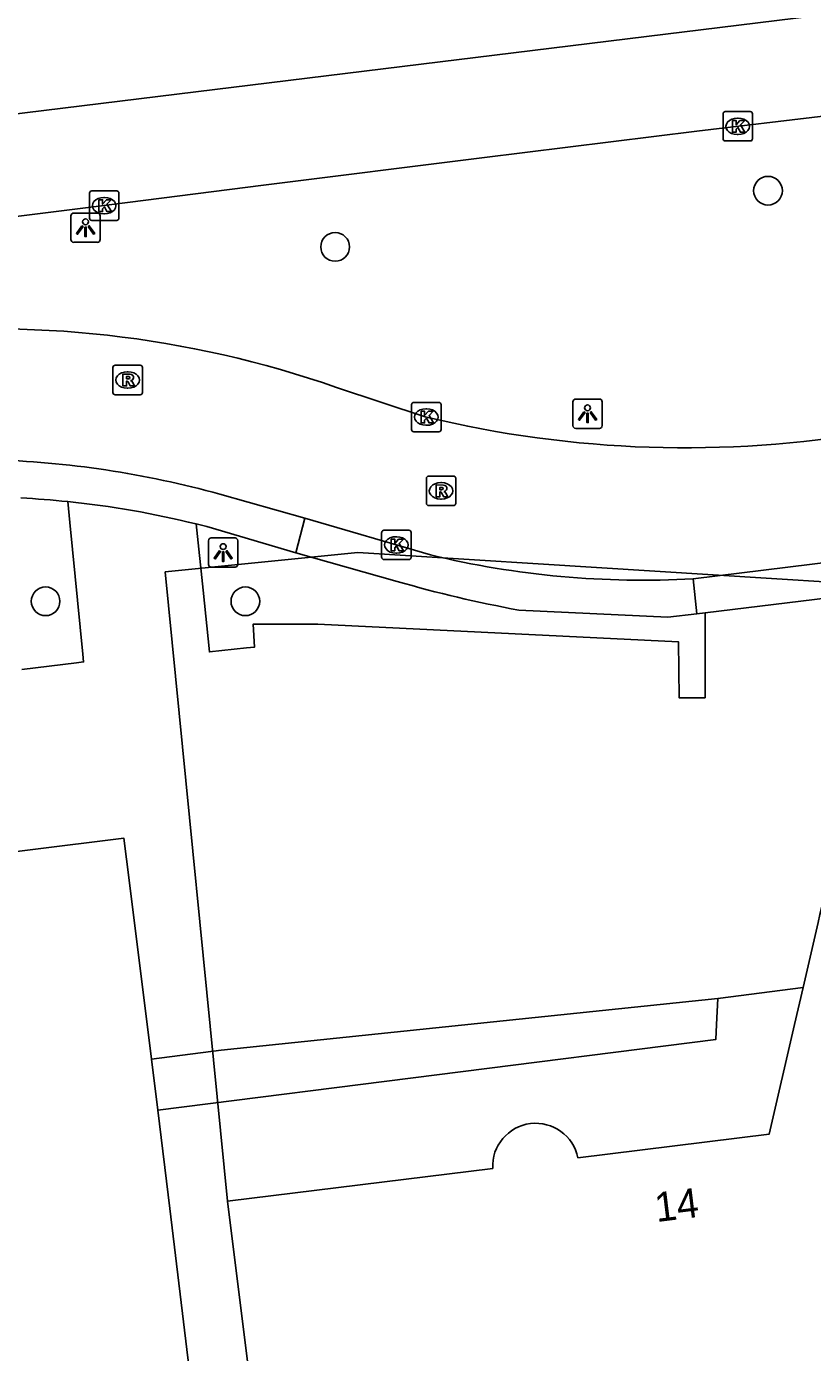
# Model space of a CAD drawing. Extents: x 161477 to 163040, y 383680 to 384868.
# Drawn here: x 161958.93 to 161985.69, y 383988.83 to 384033.98 of the extents above; entities that cross this region are included whole.
import ezdxf

# ---------------------------------------------------------------- set-up
doc = ezdxf.new("R2010")
doc.units = 0
for name, color, linetype in [('IMGEO_Boom', 7, 'Continuous'), ('IMGEO_Kolk', 7, 'Continuous'), ('IMGEO_Lichtpunt', 7, 'Continuous'), ('IMGEO_Pand', 7, 'Continuous'), ('IMGEO_Pand_nummerreeks', 7, 'Continuous'), ('IMGEO_Pand_overbouw', 7, 'Continuous'), ('IMGEO_Rijbaan_lokaal_gesloten', 7, 'Continuous'), ('IMGEO_Rijbaan_lokaal_open', 7, 'Continuous'), ('IMGEO_Rioolput', 7, 'Continuous'), ('IMGEO_Voetpad_open', 7, 'Continuous')]:
    doc.layers.add(name, color=color, linetype=linetype)

msp = doc.modelspace()

# ---------------------------------------------------------------- linework, layer by layer
at = {"layer": 'IMGEO_Boom'}
for centre in [(161984.176, 384028.393), (161969.437, 384026.48), (161959.577, 384014.412), (161966.381, 384014.412)]:
    msp.add_circle(centre, 0.489, dxfattribs=at)
at = {"layer": 'IMGEO_Kolk'}
for p, q in [((161982.645, 384030.161), (161982.645, 384031.013)), ((161982.72, 384031.087), (161983.572, 384031.087)), ((161983.646, 384031.013), (161983.646, 384030.161)), ((161983.133, 384030.867), (161983.158, 384030.867)), ((161983.572, 384030.087), (161982.72, 384030.087)), ((161983.156, 384030.307), (161983.131, 384030.307)), ((161961.072, 384027.458), (161961.072, 384028.31)), ((161961.147, 384028.384), (161961.999, 384028.384)), ((161962.073, 384028.31), (161962.073, 384027.458)), ((161961.56, 384028.164), (161961.585, 384028.164)), ((161961.999, 384027.384), (161961.147, 384027.384)), ((161961.583, 384027.604), (161961.558, 384027.604)), ((161972.041, 384020.259), (161972.041, 384021.111)), ((161972.116, 384021.185), (161972.968, 384021.185)), ((161972.529, 384020.965), (161972.554, 384020.965)), ((161973.042, 384021.111), (161973.042, 384020.259)), ((161972.968, 384020.185), (161972.116, 384020.185)), ((161972.552, 384020.405), (161972.527, 384020.405)), ((161971.021, 384015.905), (161971.021, 384016.757)), ((161971.096, 384016.831), (161971.948, 384016.831)), ((161971.509, 384016.611), (161971.534, 384016.611)), ((161972.022, 384016.757), (161972.022, 384015.905)), ((161971.532, 384016.051), (161971.507, 384016.051)), ((161971.948, 384015.831), (161971.096, 384015.831))]:
    msp.add_line(p, q, dxfattribs=at)
for points in [[(161982.645, 384030.161), (161982.645, 384031.013)], [(161982.72, 384031.087), (161983.572, 384031.087)], [(161983.646, 384031.013), (161983.646, 384030.161)], [(161982.966, 384030.787), (161983.089, 384030.787), (161983.089, 384030.636), (161983.219, 384030.787), (161983.383, 384030.787), (161983.237, 384030.636), (161983.39, 384030.387), (161983.238, 384030.387), (161983.153, 384030.551), (161983.089, 384030.484), (161983.089, 384030.387), (161982.966, 384030.387), (161982.966, 384030.787)], [(161983.572, 384030.087), (161982.72, 384030.087)], [(161961.072, 384027.458), (161961.072, 384028.31)], [(161961.147, 384028.384), (161961.999, 384028.384)], [(161962.073, 384028.31), (161962.073, 384027.458)], [(161961.393, 384028.084), (161961.516, 384028.084), (161961.516, 384027.933), (161961.646, 384028.084), (161961.81, 384028.084), (161961.664, 384027.933), (161961.817, 384027.684), (161961.665, 384027.684), (161961.58, 384027.848), (161961.516, 384027.781), (161961.516, 384027.684), (161961.393, 384027.684), (161961.393, 384028.084)], [(161961.999, 384027.384), (161961.147, 384027.384)], [(161972.041, 384020.259), (161972.041, 384021.111)], [(161972.116, 384021.185), (161972.968, 384021.185)], [(161973.042, 384021.111), (161973.042, 384020.259)], [(161972.362, 384020.885), (161972.485, 384020.885), (161972.485, 384020.734), (161972.615, 384020.885), (161972.779, 384020.885), (161972.633, 384020.734), (161972.786, 384020.485), (161972.634, 384020.485), (161972.549, 384020.649), (161972.485, 384020.582), (161972.485, 384020.485), (161972.362, 384020.485), (161972.362, 384020.885)], [(161972.968, 384020.185), (161972.116, 384020.185)], [(161971.021, 384015.905), (161971.021, 384016.757)], [(161971.096, 384016.831), (161971.948, 384016.831)], [(161971.342, 384016.531), (161971.465, 384016.531), (161971.465, 384016.38), (161971.595, 384016.531), (161971.759, 384016.531), (161971.613, 384016.38), (161971.766, 384016.131), (161971.614, 384016.131), (161971.529, 384016.295), (161971.465, 384016.228), (161971.465, 384016.131), (161971.342, 384016.131), (161971.342, 384016.531)], [(161972.022, 384016.757), (161972.022, 384015.905)], [(161971.948, 384015.831), (161971.096, 384015.831)]]:
    msp.add_lwpolyline(points, dxfattribs=at)
for centre, start, end in [((161982.722, 384031.011), 91.552, 178.448), ((161982.722, 384031.011), 91.552, 178.448), ((161983.57, 384031.011), 1.552, 88.448), ((161983.57, 384031.011), 1.552, 88.448), ((161982.722, 384030.163), 181.552, 268.448), ((161982.722, 384030.163), 181.552, 268.448), ((161983.57, 384030.163), 271.552, 358.448), ((161983.57, 384030.163), 271.552, 358.448), ((161961.149, 384028.308), 91.552, 178.448), ((161961.149, 384028.308), 91.552, 178.448), ((161961.997, 384028.308), 1.552, 88.448), ((161961.997, 384028.308), 1.552, 88.448), ((161961.149, 384027.46), 181.552, 268.448), ((161961.149, 384027.46), 181.552, 268.448), ((161961.997, 384027.46), 271.552, 358.448), ((161961.997, 384027.46), 271.552, 358.448), ((161972.118, 384021.109), 91.552, 178.448), ((161972.118, 384021.109), 91.552, 178.448), ((161972.966, 384021.109), 1.552, 88.448), ((161972.966, 384021.109), 1.552, 88.448), ((161972.118, 384020.261), 181.552, 268.448), ((161972.118, 384020.261), 181.552, 268.448), ((161972.966, 384020.261), 271.552, 358.448), ((161972.966, 384020.261), 271.552, 358.448), ((161971.098, 384016.755), 91.552, 178.448), ((161971.098, 384016.755), 91.552, 178.448), ((161971.946, 384016.755), 1.552, 88.448), ((161971.946, 384016.755), 1.552, 88.448), ((161971.098, 384015.907), 181.552, 268.448), ((161971.098, 384015.907), 181.552, 268.448), ((161971.946, 384015.907), 271.552, 358.448), ((161971.946, 384015.907), 271.552, 358.448)]:
    msp.add_arc(centre, 0.0765, start, end, dxfattribs=at)
for centre, major_axis, ratio, start_param, end_param in [((161983.132, 384030.587), (-0.387, 0.002), 0.722429, 4.712389, 7.853982), ((161983.157, 384030.587), (-0.39, 0.002), 0.717154, 1.570796, 4.712389), ((161961.559, 384027.884), (-0.387, 0.002), 0.722429, 4.712389, 7.853982), ((161961.584, 384027.884), (-0.39, 0.002), 0.717154, 1.570796, 4.712389), ((161972.528, 384020.685), (-0.387, 0.002), 0.722429, 4.712389, 7.853982), ((161972.553, 384020.685), (-0.39, 0.002), 0.717154, 1.570796, 4.712389), ((161971.508, 384016.331), (-0.387, 0.002), 0.722429, 4.712389, 7.853982), ((161971.533, 384016.331), (-0.39, 0.002), 0.717154, 1.570796, 4.712389)]:
    msp.add_ellipse(centre, major_axis=major_axis, ratio=ratio, start_param=start_param, end_param=end_param, dxfattribs=at)
at = {"layer": 'IMGEO_Lichtpunt'}
for p, q in [((161960.44, 384027.537), (161960.44, 384026.73)), ((161960.44, 384027.537), (161960.44, 384026.73)), ((161961.342, 384027.632), (161960.534, 384027.632)), ((161961.342, 384027.632), (161960.534, 384027.632)), ((161961.436, 384026.73), (161961.436, 384027.537)), ((161961.436, 384026.73), (161961.436, 384027.537)), ((161960.534, 384026.636), (161961.342, 384026.636)), ((161960.534, 384026.636), (161961.342, 384026.636)), ((161977.534, 384021.202), (161977.534, 384020.395)), ((161977.534, 384021.202), (161977.534, 384020.395)), ((161978.436, 384021.297), (161977.628, 384021.297)), ((161978.436, 384021.297), (161977.628, 384021.297)), ((161978.53, 384020.395), (161978.53, 384021.202)), ((161978.53, 384020.395), (161978.53, 384021.202)), ((161977.628, 384020.301), (161978.436, 384020.301)), ((161977.628, 384020.301), (161978.436, 384020.301)), ((161965.125, 384016.475), (161965.125, 384015.668)), ((161965.125, 384016.475), (161965.125, 384015.668)), ((161966.027, 384016.57), (161965.219, 384016.57)), ((161966.027, 384016.57), (161965.219, 384016.57)), ((161966.121, 384015.668), (161966.121, 384016.475)), ((161966.121, 384015.668), (161966.121, 384016.475)), ((161965.219, 384015.574), (161966.027, 384015.574)), ((161965.219, 384015.574), (161966.027, 384015.574))]:
    msp.add_line(p, q, dxfattribs=at)
for points in [[(161960.814, 384027.201), (161960.853, 384027.173), (161960.665, 384026.911), (161960.627, 384026.938), (161960.814, 384027.201)], [(161960.916, 384027.153), (161960.963, 384027.153), (161960.963, 384026.831), (161960.916, 384026.831), (161960.916, 384027.153)], [(161961.026, 384027.173), (161961.064, 384027.2), (161961.251, 384026.938), (161961.212, 384026.91), (161961.026, 384027.173)], [(161977.908, 384020.866), (161977.947, 384020.838), (161977.759, 384020.576), (161977.721, 384020.603), (161977.908, 384020.866)], [(161978.01, 384020.818), (161978.057, 384020.818), (161978.057, 384020.496), (161978.01, 384020.496), (161978.01, 384020.818)], [(161978.12, 384020.838), (161978.158, 384020.865), (161978.345, 384020.603), (161978.306, 384020.575), (161978.12, 384020.838)], [(161965.499, 384016.139), (161965.538, 384016.111), (161965.35, 384015.849), (161965.312, 384015.876), (161965.499, 384016.139)], [(161965.601, 384016.091), (161965.648, 384016.091), (161965.648, 384015.769), (161965.601, 384015.769), (161965.601, 384016.091)], [(161965.711, 384016.111), (161965.749, 384016.138), (161965.936, 384015.876), (161965.897, 384015.848), (161965.711, 384016.111)]]:
    msp.add_lwpolyline(points, dxfattribs=at)
for centre in [(161960.939, 384027.335), (161978.033, 384021), (161965.624, 384016.273)]:
    msp.add_circle(centre, 0.0994, dxfattribs=at)
for centre, start, end in [((161960.534, 384027.537), 90, 180), ((161960.534, 384027.537), 90, 180), ((161961.342, 384027.537), 0, 90), ((161961.342, 384027.537), 0, 90), ((161960.534, 384026.73), 180, 270), ((161960.534, 384026.73), 180, 270), ((161961.342, 384026.73), 270, 0), ((161961.342, 384026.73), 270, 360), ((161977.628, 384021.202), 90, 180), ((161977.628, 384021.202), 90, 180), ((161978.436, 384021.202), 0, 90), ((161978.436, 384021.202), 0, 90), ((161977.628, 384020.395), 180, 270), ((161977.628, 384020.395), 180, 270), ((161978.436, 384020.395), 270, 0), ((161978.436, 384020.395), 270, 360), ((161965.219, 384016.475), 90, 180), ((161965.219, 384016.475), 90, 180), ((161966.027, 384016.475), 0, 90), ((161966.027, 384016.475), 0, 90), ((161965.219, 384015.668), 180, 270), ((161965.219, 384015.668), 180, 270), ((161966.027, 384015.668), 270, 0), ((161966.027, 384015.668), 270, 360)]:
    msp.add_arc(centre, 0.0946, start, end, dxfattribs=at)
at = {"layer": 'IMGEO_Pand'}
for points in [[(161952.749, 384005.163), (161962.246, 384006.341), (161962.423, 384004.917), (161963.181, 383998.816)], [(161985.371, 384001.262), (161985.88, 384003.477), (161985.946, 384003.746), (161986.011, 384004.007)], [(161977.701, 383995.458), (161984.214, 383996.262), (161985.079, 384000), (161985.371, 384001.262)], [(161963.396, 383997.077), (161963.181, 383998.816)], [(161963.396, 383997.077), (161963.811, 383993.739), (161964.461, 383988.274), (161965.92, 383976.575), (161968.408, 383956.619), (161969.073, 383951.131), (161955.356, 383949.45), (161955.133, 383951.147), (161955.119, 383951.24), (161924.788, 383947.478)], [(161981.129, 383955.114), (161980.959, 383954.521), (161974.903, 383955.916), (161978.261, 383970.442), (161975.409, 383985.765), (161966.543, 383987.797), (161965.767, 383993.981), (161974.802, 383995.101)]]:
    msp.add_lwpolyline(points, dxfattribs=at)
msp.add_arc((161976.265, 383995.171), 1.465, 11.2833, 182.7575, dxfattribs=at)
at = {"layer": 'IMGEO_Pand_overbouw'}
for points in [[(161977.701, 383995.458), (161984.214, 383996.262), (161985.079, 384000), (161985.371, 384001.262), (161985.88, 384003.477), (161985.946, 384003.746), (161986.011, 384004.007), (161986.378, 384003.925), (161986.327, 384003.735), (161991.48, 384003.456), (161991.454, 384003.664), (161991.801, 384003.707), (161991.39, 384006.662), (161991.261, 384007.832), (161991.117, 384009.147), (161990.439, 384014.803), (161970.21, 384016.077), (161963.654, 384015.417)], [(161963.654, 384015.417), (161965.767, 383993.981), (161974.802, 383995.101)]]:
    msp.add_lwpolyline(points, dxfattribs=at)
msp.add_arc((161976.265, 383995.171), 1.465, 11.2833, 182.7575, dxfattribs=at)
at = {"layer": 'IMGEO_Rijbaan_lokaal_gesloten'}
for points in [[(161696.618, 383999.076), (161717.081, 384001.544), (161768.879, 384007.897), (161825.477, 384014.75), (161917.35, 384025.954), (162007.495, 384037.033), (162008.923, 384037.209), (162102.422, 384048.613), (162177.172, 384057.667), (162248.391, 384066.39)], [(162036.516, 384037.016), (162009.54, 384033.893), (162008.109, 384033.699), (162000, 384032.599), (161996.88, 384032.194), (161990.538, 384031.465), (161981.752, 384030.422), (161974.434, 384029.511), (161966.996, 384028.578), (161961.213, 384027.84), (161952.768, 384026.784), (161946.406, 384026.014), (161938.648, 384025.104), (161928.777, 384023.886), (161920.55, 384022.895), (161914.21, 384022.046), (161904.857, 384020.891), (161896.801, 384019.864), (161888.804, 384018.877), (161880.897, 384017.893), (161873.318, 384016.997), (161865.049, 384016.046), (161854.527, 384014.894)], [(161972.542, 384020.685), (161969.486, 384021.696)], [(161965.511, 384018.06), (161968.407, 384017.239)], [(161968.407, 384017.239), (161972.68, 384015.993)], [(161981.63, 384015.178), (161994.527, 384016.771)]]:
    msp.add_lwpolyline(points, dxfattribs=at)
for centre, radius, start, end in [((161957.72, 383988.002), 35.689, 70.7507, 96.4837), ((161981.375, 384057.405), 37.767, 256.4746, 279.7582), ((161956.72, 383986.183), 33.067, 74.5816, 88.3289), ((161979.916, 384045.901), 30.771, 256.3999, 273.194)]:
    msp.add_arc(centre, radius, start, end, dxfattribs=at)
at = {"layer": 'IMGEO_Rijbaan_lokaal_open'}
for points in [[(161960.334, 384017.808), (161960.403, 384017.097), (161960.843, 384012.611), (161960.869, 384012.347), (161960.628, 384012.317), (161958.768, 384012.088)], [(161982.034, 384014.017), (161982.035, 384013.809), (161982.035, 384013.634), (161982.035, 384011.125), (161981.148, 384011.125), (161981.124, 384013.033), (161968.843, 384013.634), (161966.65, 384013.634), (161966.691, 384012.851), (161966.417, 384012.822), (161965.157, 384012.69), (161964.939, 384014.793), (161964.705, 384017.045)], [(161994.043, 384015.479), (161982.034, 384014.017)], [(161982.473, 384000.882), (161985.371, 384001.262)], [(161963.181, 383998.816), (161965.556, 383999.127), (161982.473, 384000.882)]]:
    msp.add_lwpolyline(points, dxfattribs=at)
msp.add_arc((161957.082, 383986.276), 31.699, 76.0849, 84.1116, dxfattribs=at)
at = {"layer": 'IMGEO_Rioolput'}
for p, q in [((161961.872, 384021.522), (161961.872, 384022.374)), ((161961.947, 384022.448), (161962.799, 384022.448)), ((161962.873, 384022.374), (161962.873, 384021.522)), ((161962.36, 384022.228), (161962.385, 384022.228)), ((161962.799, 384021.448), (161961.947, 384021.448)), ((161962.383, 384021.668), (161962.358, 384021.668)), ((161972.543, 384017.747), (161972.543, 384018.599)), ((161972.618, 384018.673), (161973.47, 384018.673)), ((161973.031, 384018.453), (161973.056, 384018.453)), ((161973.544, 384018.599), (161973.544, 384017.747)), ((161973.054, 384017.893), (161973.029, 384017.893)), ((161973.47, 384017.673), (161972.618, 384017.673))]:
    msp.add_line(p, q, dxfattribs=at)
for points in [[(161961.872, 384021.522), (161961.872, 384022.374)], [(161961.947, 384022.448), (161962.799, 384022.448)], [(161962.873, 384022.374), (161962.873, 384021.522)], [(161962.461, 384022.146), (161962.209, 384022.148), (161962.209, 384021.748)], [(161962.209, 384021.748), (161962.333, 384021.748), (161962.333, 384021.91), (161962.344, 384021.91)], [(161962.387, 384022.067), (161962.333, 384022.067), (161962.333, 384021.986)], [(161962.333, 384021.986), (161962.385, 384021.986)], [(161962.391, 384021.881), (161962.462, 384021.748), (161962.602, 384021.748), (161962.537, 384021.874)], [(161962.799, 384021.448), (161961.947, 384021.448)], [(161972.543, 384017.747), (161972.543, 384018.599)], [(161972.618, 384018.673), (161973.47, 384018.673)], [(161973.132, 384018.371), (161972.88, 384018.373), (161972.88, 384017.973)], [(161973.058, 384018.292), (161973.004, 384018.292), (161973.004, 384018.211)], [(161973.544, 384018.599), (161973.544, 384017.747)], [(161972.88, 384017.973), (161973.004, 384017.973), (161973.004, 384018.135), (161973.015, 384018.135)], [(161973.004, 384018.211), (161973.056, 384018.211)], [(161973.062, 384018.106), (161973.133, 384017.973), (161973.273, 384017.973), (161973.208, 384018.099)], [(161973.47, 384017.673), (161972.618, 384017.673)]]:
    msp.add_lwpolyline(points, dxfattribs=at)
for centre, radius, start, end in [((161961.949, 384022.372), 0.0765, 91.552, 178.448), ((161961.949, 384022.372), 0.0765, 91.552, 178.448), ((161962.797, 384022.372), 0.0765, 1.552, 88.448), ((161962.797, 384022.372), 0.0765, 1.552, 88.448), ((161962.343, 384021.857), 0.0533, 26.0293, 88.6989), ((161962.369, 384022.175), 0.19, 274.7715, 282.9687), ((161962.393, 384021.971), 0.0964, 77.0061, 93.1865), ((161962.407, 384022.028), 0.0378, 276.6634, 79.6772), ((161962.46, 384022.036), 0.109, 350.3612, 89.416), ((161962.458, 384022.036), 0.112, 277.5842, 350.9817), ((161962.442, 384021.821), 0.108, 29.5134, 73.7905), ((161961.949, 384021.524), 0.0765, 181.552, 268.448), ((161961.949, 384021.524), 0.0765, 181.552, 268.448), ((161962.797, 384021.524), 0.0765, 271.552, 358.448), ((161962.797, 384021.524), 0.0765, 271.552, 358.448), ((161972.62, 384018.597), 0.0765, 91.552, 178.448), ((161972.62, 384018.597), 0.0765, 91.552, 178.448), ((161973.064, 384018.196), 0.0964, 77.0061, 93.1865), ((161973.078, 384018.253), 0.0378, 276.6634, 79.6772), ((161973.131, 384018.261), 0.109, 350.3612, 89.416), ((161973.129, 384018.261), 0.112, 277.5842, 350.9817), ((161973.468, 384018.597), 0.0765, 1.552, 88.448), ((161973.468, 384018.597), 0.0765, 1.552, 88.448), ((161973.014, 384018.082), 0.0533, 26.0293, 88.6989), ((161973.04, 384018.4), 0.19, 274.7715, 282.9687), ((161973.113, 384018.046), 0.108, 29.5134, 73.7905), ((161972.62, 384017.749), 0.0765, 181.552, 268.448), ((161972.62, 384017.749), 0.0765, 181.552, 268.448), ((161973.468, 384017.749), 0.0765, 271.552, 358.448), ((161973.468, 384017.749), 0.0765, 271.552, 358.448)]:
    msp.add_arc(centre, radius, start, end, dxfattribs=at)
for centre, major_axis, ratio, start_param, end_param in [((161962.359, 384021.948), (-0.387, 0.002), 0.722429, 4.712389, 7.853982), ((161962.384, 384021.948), (-0.39, 0.002), 0.717154, 1.570796, 4.712389), ((161973.03, 384018.173), (-0.387, 0.002), 0.722429, 4.712389, 7.853982), ((161973.055, 384018.173), (-0.39, 0.002), 0.717154, 1.570796, 4.712389)]:
    msp.add_ellipse(centre, major_axis=major_axis, ratio=ratio, start_param=start_param, end_param=end_param, dxfattribs=at)
at = {"layer": 'IMGEO_Voetpad_open'}
for points in [[(161968.099, 384016.067), (161965.069, 384016.953), (161964.705, 384017.045)], [(161968.099, 384016.067), (161968.407, 384017.239)], [(161971.545, 384015.089), (161968.099, 384016.067)], [(161981.63, 384015.178), (161981.753, 384013.983)], [(161981.753, 384013.983), (161980.764, 384013.87), (161975.695, 384014.111)], [(161982.034, 384014.017), (161981.753, 384013.983)], [(161982.473, 384000.882), (161982.424, 384000), (161982.395, 383999.485), (161963.396, 383997.077)]]:
    msp.add_lwpolyline(points, dxfattribs=at)
for centre, radius, start, end in [((161956.938, 383984.085), 33.893, 84.2494, 86.9641), ((161983.206, 384055.277), 41.845, 253.8192, 259.6597)]:
    msp.add_arc(centre, radius, start, end, dxfattribs=at)

# ---------------------------------------------------------------- texts
at = {"layer": 'IMGEO_Pand_nummerreeks'}
msp.add_text('14', height=1, rotation=7.0359, dxfattribs=at).set_placement((161980.383, 383993.27))

doc.saveas('drawing.dxf')
